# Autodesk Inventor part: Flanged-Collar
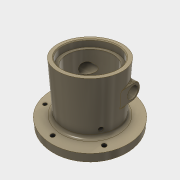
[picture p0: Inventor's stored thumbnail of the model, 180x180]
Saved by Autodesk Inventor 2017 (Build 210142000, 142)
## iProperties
Shininess: 64.0
Length Units: 11269
Angle Units: 11279
Time Units: 11290
Mass Units: 11283
Length Display Precision: 3
Angle Display Precision: 2
Compacted: True
Part Number: Flanged-Collar
Document SubType Name: Modeling
Created: 2004-01
Designer: Administrator
Manufacturer: Standard
Standards Organization: Custom
Density: 1 g/cm^3
Material: Generic
Appearance: Wheat
Density: 0.0
Volumn: 0.0
Area: 0.0
PropertySet Name: Model Information
Control State: 0
Master: False
Checked Out: False
Author: Administrator
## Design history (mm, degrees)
sketch "Sketch1"
  geometry: C1 r 26.25 at (0, 0); 1 further point
  constraints: 1 centre point, 1 coincident
  dimensions: "d0" = 52.5 diameter of C1
extrude "Extrusion1" new body sketch "Sketch1" distance "d1" = 5; taper "d2" = 0 deg
sketch "Sketch2"
  geometry: C1 r 26.25 at (0, 0) reference; C2 r 17.5 at (0, 0)
  constraints: 1 centre point, 1 coincident
  dimensions: "d3" = 35 diameter of C2
extrude "Extrusion2" join sketch "Sketch2" distance "d4" = 30; taper "d5" = 0 deg
fillet "Fillet1" dims "d6" = 2
sketch "Sketch3"
  geometry: L1 (0, 0)-(0, 32.017); L2 (0, 0)-(-27.026, -15.603); L3 (0, 0)-(27.791, -16.045); L4 (0, 0)-(0, -33.044); C1 r 19.5 at (0, 0) reference; A1 r 22.5 centre (0, 0) between (0, 22.5) and (-19.486, -11.25); 2 further points
  constraints: 8 end point, 4 point on circle, 4 point on line, 2 vertical, 1 centre point, 1 coincident
  dimensions: "d7" = 45 diameter of A1; "d8" = 60 deg angle of L4 L2; "d9" = 60 deg angle of L3 L4
hole "Hole1" sketch "Sketch3" at (0, 22.5), (-19.486, -11.25), (0, -22.5), (19.486, -11.25) diameter "d10" = 2.459; stored, may be unused: countersink angle "d14" = 82 deg, drill point angle "d16" = 118 deg; dims "d11" = 6, "d12" = 4, "d13" = 2, "d15" = 8
sketch "Sketch4"
  geometry: L1 (-17.5, 35)-(17.5, 35) reference; L2 (-17.5, 7)-(17.5, 7) reference; L3 (-26.25, 0)-(26.25, 0) reference; L4 (0, 35)-(-15, 35); L5 (-15, 35)-(-15, 31); L6 (0, 0)-(-15, 0); L7 (-15, 0)-(-15, 3.5); L8 (-13, 3.5)-(-13, 31); L9 (0, 35)-(0, 0); L10 (-15, 31)-(-13, 31); L11 (-15, 3.5)-(-13, 3.5)
  constraints: 16 end point, 2 horizontal, 2 midpoint, 2 parallel, 1 collinear, 1 perpendicular, 1 vertical
  dimensions: "d17" = 4 distance of L4.end L5.end; "d18" = 3.5 distance of L6.end L7.end; "d21" = 15 distance between parallel lines of L7 L9; "d59" = 2 distance of L5.end L8.end
revolve "Revolution1" sketch "Sketch4" stored, may be unused: angle "d22" = 90 deg
sketch "Sketch5"
  geometry: C1 r 15 at (0, 0) reference; C2 r 18 at (0, 0); C3 r 20 at (0, 0)
  constraints: 2 centre point
  dimensions: "d24" = 2 radial gap between concentric circles of C3 C2; "d25" = 3 radial gap between concentric circles of C2 C1
extrude "Extrusion3" cut sketch "Sketch5" distance "d26" = 1; taper "d27" = 0 deg
workplane "Work Plane1"
sketch "Sketch6"
  geometry: L1 (-13, -1.5)-(13, -1.5) reference; L2 (-13, 26)-(13, 26) reference; L3 (0, -12)-(0, 37) reference; L4 (0, 11.021)-(8, 11.021); L5 (8, 11.021)-(8, 21.021); L6 (8, 21.021)-(0, 21.021); L7 (0, 21.021)-(0, 11.021); L8 (13, 26)-(13, 16.021); A1 r 5 centre (8, 16.021) between (8, 21.021) and (13, 16.021)
  constraints: 10 end point, 2 parallel, 2 point on circle, 1 centre point, 1 horizontal, 1 midpoint, 1 perpendicular, 1 point on line, 1 tangent, 1 vertical
  dimensions: "d28" = 10 diameter of A1
extrude "Extrusion4" join sketch "Sketch6" stored distance "d29" = 2; taper "d30" = 0 deg
sketch "Sketch7"
  geometry: A1 r 5 centre (-16.021, 8) between (-11.021, 8) and (-21.021, 8) reference
hole "Hole2" sketch "Sketch7" at (-16.021, 8) diameter "d31" = 7; stored, may be unused: countersink angle "d35" = 82 deg, drill point angle "d37" = 118 deg; dims "d32" = 6, "d33" = 4, "d34" = 2, "d36" = 15
mirror "Mirror1"
workplane "Work Plane2"
sketch "Sketch8"
  geometry: L1 (-26.25, -5)-(26.25, -5) reference; 2 further points
  constraints: 1 midpoint, 1 vertical alignment
  dimensions: "d38" = 9.5 distance from line of point (0, 4.5) L1
hole "Hole3" sketch "Sketch8" at (0, 4.5) diameter "d39" = 2.459; stored, may be unused: countersink angle "d43" = 82 deg, drill point angle "d45" = 118 deg; dims "d40" = 6, "d41" = 4, "d42" = 2, "d44" = 8
pattern_circular "Circular Pattern1" dims angle "d48" = 360 deg
chamfer "Chamfer1" distance "d49" = 0.5; stored, may be unused: second distance "d50" = 2, angle "d51" = 45 deg
chamfer "Chamfer2" distance "d52" = 0.5; stored, may be unused: second distance "d53" = 2, angle "d54" = 45 deg
fillet "Fillet2" dims "d55" = 0.5
fillet "Fillet3" dims "d56" = 0.5
fillet "Fillet4" dims "d57" = 0.5
fillet "Fillet5" dims "d58" = 0.5
workaxis "Work Axis1"
body "Solid1"
node "Projected Loop1"
node "Projected Loop2"
